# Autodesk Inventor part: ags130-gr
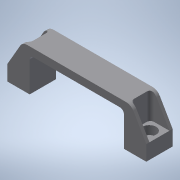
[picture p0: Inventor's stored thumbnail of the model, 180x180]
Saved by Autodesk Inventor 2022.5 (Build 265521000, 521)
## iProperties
Created: 2016-12
Part Number: ags130-gr
Material: 一般
Document SubType Name: Modeling
Designer: imaocorp
Density: 1 g/cm^3
Appearance: 既定
Author: imaocorp
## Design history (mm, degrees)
node "ags130-gr.x_t1"
node "ags130-gr"
node "Base1"
